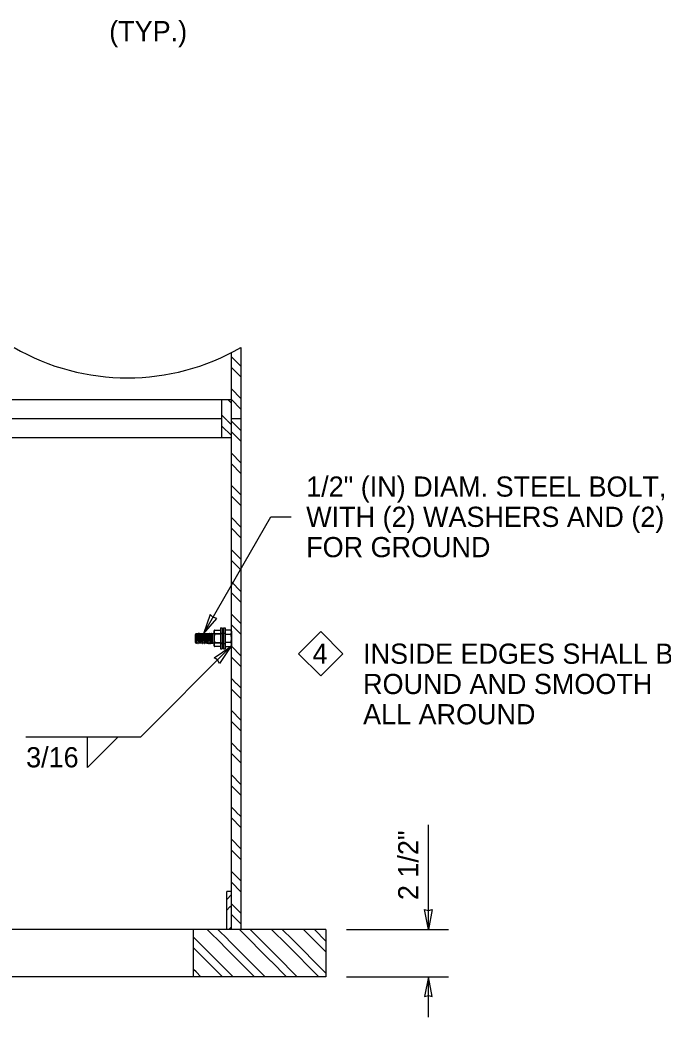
# Model space of a CAD drawing. Extents: x 99862 to 104211, y 98939 to 111076.
# Drawn here: x 101290 to 101800, y 109585 to 110375 of the extents above; entities that cross this region are included whole.
import ezdxf

# ---------------------------------------------------------------- set-up
doc = ezdxf.new("R2010")
doc.units = 0
for name, color, linetype in [('Level 10', 7, 'Continuous'), ('Level 11', 7, 'Continuous'), ('Level 15', 7, 'Continuous'), ('Level 2', 7, 'Continuous'), ('Level 20', 7, 'Continuous'), ('Level 3', 7, 'Continuous'), ('Level 5', 7, 'Continuous'), ('Level 62', 7, 'Continuous'), ('Level 9', 7, 'Continuous')]:
    doc.layers.add(name, color=color, linetype=linetype)

msp = doc.modelspace()

# ---------------------------------------------------------------- linework, layer by layer
at = {"layer": 'Level 11'}
for p, q in [((101457.91, 110108.52), (101461.88, 110104.55)), ((101461.9, 110104.53), (101465.41, 110101.02)), ((101457.91, 110100.03), (101465.41, 110092.53)), ((101457.91, 110083.02), (101465.41, 110075.52)), ((101457.91, 110074.53), (101465.41, 110067.03)), ((101457.91, 110057.52), (101461.86, 110053.57)), ((101457.91, 110049.03), (101465.41, 110041.53)), ((101461.88, 110053.55), (101465.41, 110050.02)), ((101457.91, 110032.02), (101465.41, 110024.52)), ((101457.91, 110023.53), (101465.41, 110016.03)), ((101457.91, 110006.52), (101461.83, 110002.59)), ((101461.86, 110002.57), (101465.41, 109999.02)), ((101457.91, 109998.03), (101465.41, 109990.53)), ((101457.91, 109981.02), (101465.41, 109973.52)), ((101457.91, 109972.53), (101465.41, 109965.03)), ((101457.91, 109955.52), (101461.81, 109951.61)), ((101457.91, 109947.03), (101465.41, 109939.53)), ((101461.83, 109951.59), (101465.41, 109948.02)), ((101457.91, 109930.02), (101465.41, 109922.52)), ((101457.91, 109921.53), (101465.41, 109914.03)), ((101457.91, 109904.52), (101461.79, 109900.64)), ((101461.81, 109900.61), (101465.41, 109897.02)), ((101457.91, 109896.03), (101465.41, 109888.53)), ((101457.91, 109879.02), (101465.41, 109871.52)), ((101457.91, 109870.53), (101465.41, 109863.03)), ((101457.91, 109853.52), (101461.77, 109849.66)), ((101457.91, 109845.03), (101465.41, 109837.53)), ((101461.79, 109849.64), (101465.41, 109846.02)), ((101457.91, 109828.02), (101465.41, 109820.52)), ((101457.91, 109819.53), (101465.41, 109812.03)), ((101457.91, 109802.52), (101461.74, 109798.68)), ((101461.77, 109798.66), (101465.41, 109795.02)), ((101457.91, 109794.03), (101465.41, 109786.53)), ((101457.91, 109777.02), (101465.41, 109769.52)), ((101457.91, 109768.53), (101465.41, 109761.03)), ((101457.91, 109751.52), (101461.72, 109747.7)), ((101457.91, 109743.03), (101465.41, 109735.53)), ((101461.74, 109747.68), (101465.41, 109744.02)), ((101457.91, 109726.02), (101465.41, 109718.52)), ((101457.91, 109717.53), (101465.41, 109710.03)), ((101457.91, 109700.52), (101461.7, 109696.72)), ((101461.72, 109696.7), (101465.41, 109693.02)), ((101457.91, 109692.03), (101465.41, 109684.53)), ((101454.16, 109678.43), (101457.91, 109682.18)), ((101454.16, 109669.95), (101456.61, 109672.4)), ((101456.64, 109672.43), (101457.91, 109673.7)), ((101457.91, 109675.02), (101465.41, 109667.52)), ((101457.91, 109666.53), (101465.41, 109659.03)), ((101427.91, 109654.65), (101142.91, 109654.65)), ((101451.06, 109642.27), (101438.68, 109654.65)), ((101455.3, 109646.51), (101447.17, 109654.65)), ((101455.87, 109654.65), (101457.91, 109656.68)), ((101489.28, 109629.54), (101464.18, 109654.65)), ((101493.53, 109633.79), (101472.67, 109654.65)), ((101502.03, 109642.29), (101489.68, 109654.65)), ((101506.28, 109646.54), (101498.17, 109654.65)), ((101532.91, 109636.92), (101515.18, 109654.65)), ((101532.91, 109645.41), (101523.67, 109654.65)), ((101442.55, 109633.76), (101427.91, 109648.41)), ((101480.78, 109621.04), (101455.32, 109646.49)), ((101531.75, 109621.06), (101506.3, 109646.51)), ((101438.31, 109629.52), (101427.91, 109639.92)), ((101476.18, 109617.15), (101451.08, 109642.25)), ((101527.18, 109617.15), (101502.06, 109642.27)), ((101459.17, 109617.15), (101442.57, 109633.74)), ((101510.17, 109617.15), (101493.55, 109633.76)), ((101429.8, 109621.01), (101427.91, 109622.9)), ((101450.68, 109617.15), (101438.33, 109629.5)), ((101501.68, 109617.15), (101489.31, 109629.52)), ((101427.91, 109617.15), (101142.91, 109617.15)), ((101433.67, 109617.15), (101429.82, 109620.99)), ((101484.67, 109617.15), (101480.8, 109621.01)), ((101532.91, 109619.91), (101531.78, 109621.04))]:
    msp.add_line(p, q, dxfattribs=at)
at = {"layer": 'Level 15'}
for p, q in [((101435.72, 109889.02), (101489.19, 109981.64)), ((101489.2, 109981.64), (101505.2, 109981.64)), ((101457.48, 109878.81), (101385.74, 109807.08)), ((101385.74, 109807.08), (101294.8, 109807.08)), ((101343.65, 109783.08), (101367.65, 109807.08)), ((101343.65, 109783.08), (101343.65, 109807.08)), ((101614.16, 109654.65), (101614.16, 109737.64)), ((101549.22, 109654.65), (101630.16, 109654.65)), ((101549.22, 109617.15), (101630.16, 109617.15)), ((101614.16, 109585.15), (101614.16, 109617.15))]:
    msp.add_line(p, q, dxfattribs=at)
for points in [[(101435.72, 109889.02), (101446.25, 109901.1), (101443.22, 109902.01), (101440.91, 109904.19)], [(101457.48, 109878.81), (101448.54, 109865.51), (101446.87, 109868.21), (101444.18, 109869.87)], [(101614.16, 109654.65), (101611.07, 109670.37), (101614.16, 109669.64), (101617.24, 109670.37)], [(101614.16, 109617.15), (101611.07, 109601.42), (101614.16, 109602.15), (101617.24, 109601.42)]]:
    msp.add_lwpolyline(points, close=True, dxfattribs=at)
at = {"layer": 'Level 2'}
for p, q in [((101427.91, 109617.15), (101427.91, 109654.65)), ((101532.91, 109654.65), (101427.91, 109654.65)), ((101532.91, 109654.65), (101532.91, 109617.15)), ((101532.91, 109617.15), (101427.91, 109617.15))]:
    msp.add_line(p, q, dxfattribs=at)
msp.add_lwpolyline([(101457.48, 109878.81), (101457.92, 109878.81), (101457.92, 109879.59)], close=True, dxfattribs=at)
at = {"layer": 'Level 20'}
msp.add_lwpolyline([(101528.78, 109890.72), (101546.34, 109873.17), (101528.78, 109855.62), (101511.23, 109873.17)], close=True, dxfattribs=at)
at = {"layer": 'Level 3'}
for p, q in [((101457.91, 109654.65), (101457.91, 110111.8)), ((101465.41, 110115.9), (101465.41, 109654.65)), ((101112.91, 110074.65), (101457.91, 110074.65)), ((101450.41, 110044.65), (101450.41, 110074.65)), ((101457.91, 110071.68), (101454.94, 110074.65)), ((101120.41, 110059.65), (101450.41, 110059.65)), ((101454.36, 110058.16), (101450.41, 110062.12)), ((101457.91, 110054.62), (101454.41, 110058.12)), ((101457.91, 110059.65), (101465.41, 110059.65)), ((101457.91, 110046.13), (101450.41, 110053.63)), ((101112.91, 110044.65), (101457.91, 110044.65)), ((101454.16, 109654.65), (101454.16, 109684.65)), ((101457.91, 109684.65), (101454.16, 109684.65)), ((101465.41, 109654.65), (101457.91, 109654.65))]:
    msp.add_line(p, q, dxfattribs=at)
msp.add_arc((101375.41, 110271.78), 180, 240, 300, dxfattribs=at)
at = {"layer": 'Level 5'}
for p, q in [((101429.77, 109889.02), (101429.77, 109881.52)), ((101451.6, 109889.02), (101429.77, 109889.02)), ((101449.1, 109889.05), (101449.1, 109881.55)), ((101451.6, 109889.02), (101451.6, 109881.52)), ((101452.91, 109889.05), (101452.91, 109881.55)), ((101451.6, 109881.52), (101429.77, 109881.52))]:
    msp.add_line(p, q, dxfattribs=at)
at = {"layer": 'Level 62'}
for points, degree in [([(101429.77, 109885.18), (101429.87, 109883.56), (101429.95, 109882.35), (101430.01, 109881.81), (101430.14, 109880.61), (101430.28, 109882.61), (101430.43, 109885.81), (101430.5, 109887.51), (101430.59, 109888.84), (101430.7, 109889.02)], 4), ([(101429.77, 109885.22), (101429.77, 109885.21), (101429.77, 109885.2), (101429.77, 109885.18)], 3), ([(101430.7, 109889.02), (101430.75, 109889.12), (101430.8, 109888.82), (101430.84, 109888.26), (101430.97, 109886.29), (101431.12, 109883.09), (101431.25, 109881.83), (101431.39, 109880.58), (101431.53, 109882.53), (101431.67, 109885.73), (101431.81, 109888.95), (101431.94, 109890.23), (101432.08, 109888.31), (101432.22, 109886.39), (101432.37, 109883.18), (101432.5, 109881.86), (101432.64, 109880.55), (101432.77, 109882.44), (101432.92, 109885.67)], 4), ([(101432.92, 109885.67), (101432.99, 109887.43), (101433.08, 109888.84), (101433.2, 109889.02)], 3), ([(101433.2, 109889.02), (101433.25, 109889.11), (101433.3, 109888.85), (101433.34, 109888.35), (101433.47, 109886.48), (101433.61, 109883.26), (101433.74, 109881.9), (101433.88, 109880.52), (101434.02, 109882.38), (101434.16, 109885.59), (101434.3, 109888.82), (101434.44, 109890.21), (101434.58, 109888.38), (101434.72, 109886.57), (101434.86, 109883.35), (101434.99, 109881.93), (101435.13, 109880.5), (101435.27, 109882.29), (101435.41, 109885.52), (101435.49, 109887.36), (101435.58, 109888.83), (101435.7, 109889.02)], 4), ([(101435.7, 109889.02), (101435.75, 109889.11), (101435.79, 109888.88), (101435.83, 109888.43), (101435.96, 109886.66), (101436.1, 109883.43), (101436.24, 109881.96), (101436.38, 109880.48), (101436.52, 109882.22), (101436.66, 109885.44), (101436.73, 109887.31), (101436.83, 109888.83), (101436.95, 109889.02)], 4), ([(101436.95, 109889.02), (101437, 109889.11), (101437.04, 109888.89), (101437.07, 109888.47), (101437.21, 109886.75), (101437.35, 109883.52), (101437.48, 109881.99), (101437.63, 109880.46), (101437.76, 109882.15), (101437.9, 109885.38), (101437.98, 109887.29), (101438.08, 109888.84), (101438.2, 109889.02)], 4), ([(101438.2, 109889.02), (101438.25, 109889.1), (101438.28, 109888.9), (101438.32, 109888.5), (101438.46, 109886.85), (101438.59, 109883.61), (101438.73, 109882.02), (101438.87, 109880.43), (101439.01, 109882.08), (101439.15, 109885.31), (101439.23, 109887.24), (101439.33, 109888.83), (101439.45, 109889.02)], 4), ([(101439.45, 109889.02), (101439.49, 109889.1), (101439.53, 109888.92), (101439.56, 109888.54), (101439.7, 109886.94), (101439.84, 109883.7), (101439.97, 109882.06), (101440.12, 109880.42), (101440.26, 109882), (101440.39, 109885.23), (101440.53, 109888.47), (101440.67, 109890.13), (101440.81, 109888.57), (101440.94, 109887.03), (101441.08, 109883.79), (101441.23, 109882.1), (101441.37, 109880.4), (101441.5, 109881.93), (101441.64, 109885.17), (101441.77, 109888.39), (101441.92, 109890.12), (101442.06, 109888.61), (101442.19, 109887.11), (101442.33, 109883.88), (101442.47, 109882.14), (101442.61, 109880.39), (101442.74, 109881.87), (101442.88, 109885.1), (101442.97, 109887.13), (101443.08, 109888.83), (101443.2, 109889.02)], 4)]:
    msp.add_open_spline(points, degree=degree, dxfattribs=at)
at = {"layer": 'Level 9'}
for p, q in [((101444.1, 109890.93), (101444.61, 109891.8)), ((101444.1, 109890.93), (101444.1, 109890.25)), ((101444.1, 109890.93), (101444.1, 109890.24)), ((101444.1, 109890.93), (101444.1, 109890.24)), ((101444.61, 109891.8), (101449.1, 109891.8)), ((101449.1, 109891.8), (101449.1, 109888.55)), ((101449.21, 109893.64), (101449.21, 109876.97)), ((101449.21, 109893.64), (101450.46, 109893.64)), ((101450.46, 109893.64), (101450.46, 109876.97)), ((101451.66, 109893.64), (101451.66, 109876.97)), ((101451.66, 109893.64), (101452.91, 109893.64)), ((101452.91, 109893.64), (101452.91, 109876.97)), ((101457.41, 109891.8), (101452.91, 109891.8)), ((101452.91, 109891.8), (101452.91, 109888.55)), ((101457.91, 109890.93), (101457.41, 109891.8)), ((101457.91, 109890.93), (101457.91, 109890.25)), ((101457.91, 109890.93), (101457.91, 109890.24)), ((101457.91, 109890.93), (101457.91, 109890.24)), ((101429.77, 109889.03), (101429.25, 109888.12)), ((101429.25, 109888.12), (101429.25, 109882.42)), ((101444.1, 109890.24), (101444.1, 109890.25)), ((101444.1, 109890.24), (101444.1, 109890.12)), ((101444.1, 109890.1), (101444.1, 109890.12)), ((101444.1, 109890.12), (101444.1, 109885.31)), ((101444.1, 109890.12), (101444.1, 109885.31)), ((101444.1, 109890.1), (101444.1, 109885.45)), ((101444.1, 109885.31), (101444.1, 109885.45)), ((101444.1, 109885.31), (101444.1, 109879.68)), ((101444.1, 109885.17), (101444.1, 109885.31)), ((101444.1, 109879.68), (101444.1, 109885.31)), ((101444.1, 109885.31), (101444.1, 109885.31)), ((101444.1, 109885.17), (101444.1, 109880.47)), ((101449.1, 109888.55), (101444.61, 109888.55)), ((101449.21, 109889.48), (101450.46, 109889.48)), ((101451.66, 109889.48), (101452.91, 109889.48)), ((101452.91, 109888.55), (101457.41, 109888.55)), ((101452.91, 109888.55), (101452.91, 109882.06)), ((101457.91, 109890.24), (101457.91, 109890.25)), ((101457.91, 109890.24), (101457.91, 109890.12)), ((101457.91, 109890.1), (101457.91, 109890.12)), ((101457.91, 109890.12), (101457.91, 109885.31)), ((101457.91, 109890.12), (101457.91, 109885.31)), ((101457.91, 109890.1), (101457.91, 109885.45)), ((101457.91, 109885.31), (101457.91, 109885.45)), ((101457.91, 109885.31), (101457.91, 109879.68)), ((101457.91, 109885.17), (101457.91, 109885.31)), ((101457.91, 109879.68), (101457.91, 109885.31)), ((101457.91, 109885.31), (101457.91, 109885.31)), ((101457.91, 109885.17), (101457.91, 109880.47)), ((101429.25, 109882.42), (101429.76, 109881.53)), ((101444.1, 109880.4), (101444.1, 109880.47)), ((101444.1, 109880.4), (101444.1, 109879.68)), ((101444.1, 109879.68), (101444.1, 109879.68)), ((101444.61, 109878.81), (101444.1, 109879.68)), ((101444.61, 109882.06), (101449.1, 109882.06)), ((101449.1, 109878.81), (101444.61, 109878.81)), ((101449.1, 109882.06), (101449.1, 109882.06)), ((101449.1, 109882.06), (101449.1, 109878.81)), ((101449.21, 109881.13), (101450.46, 109881.13)), ((101449.21, 109876.97), (101450.46, 109876.97)), ((101451.66, 109881.13), (101452.91, 109881.13)), ((101451.66, 109876.97), (101452.91, 109876.97)), ((101452.91, 109882.06), (101452.91, 109882.06)), ((101452.91, 109882.06), (101452.91, 109878.81)), ((101457.41, 109882.06), (101452.91, 109882.06)), ((101452.91, 109878.81), (101457.41, 109878.81)), ((101457.4, 109878.81), (101457.91, 109879.68)), ((101457.91, 109880.4), (101457.91, 109880.47)), ((101457.91, 109880.4), (101457.91, 109879.68)), ((101457.91, 109879.68), (101457.91, 109879.68))]:
    msp.add_line(p, q, dxfattribs=at)
for points, degree in [([(101444.1, 109890.24), (101444.1, 109890.25), (101444.11, 109890.27), (101444.11, 109890.29), (101444.13, 109890.8), (101444.32, 109891.31), (101444.61, 109891.8)], 3), ([(101444.61, 109891.8), (101444.31, 109891.29), (101444.12, 109890.78), (101444.1, 109890.25)], 2), ([(101444.1, 109890.24), (101444.12, 109890.77), (101444.31, 109891.29), (101444.61, 109891.8)], 2), ([(101444.61, 109891.8), (101444.61, 109891.8), (101444.61, 109891.8), (101444.61, 109891.8)], 2), ([(101457.91, 109890.24), (101457.91, 109890.25), (101457.91, 109890.27), (101457.91, 109890.29), (101457.88, 109890.8), (101457.69, 109891.31), (101457.41, 109891.8)], 3), ([(101457.41, 109891.8), (101457.41, 109891.8), (101457.41, 109891.8), (101457.41, 109891.8)], 2), ([(101457.41, 109891.8), (101457.7, 109891.29), (101457.89, 109890.78), (101457.91, 109890.25)], 2), ([(101457.91, 109890.24), (101457.89, 109890.77), (101457.7, 109891.29), (101457.41, 109891.8)], 2), ([(101429.76, 109881.53), (101429.76, 109881.53), (101429.76, 109881.85), (101429.77, 109883.07), (101429.77, 109884.01), (101429.77, 109885.96), (101429.77, 109886.96), (101429.77, 109888.47), (101429.77, 109888.94), (101429.77, 109889.03), (101429.77, 109889.03), (101429.77, 109889.02)], 3), ([(101429.77, 109888.13), (101429.77, 109887.48), (101429.77, 109886.54), (101429.77, 109884.59), (101429.77, 109883.58), (101429.77, 109882.1), (101429.76, 109881.62), (101429.76, 109881.53), (101429.76, 109881.53), (101429.76, 109881.53)], 3), ([(101429.77, 109889.02), (101429.77, 109888.98), (101429.77, 109888.67), (101429.77, 109888.13)], 2), ([(101429.77, 109889.02), (101429.77, 109889.02), (101429.77, 109889.02), (101429.77, 109889.02)], 2), ([(101444.61, 109888.55), (101444.31, 109889.06), (101444.12, 109889.59), (101444.1, 109890.12)], 2), ([(101444.61, 109888.55), (101444.31, 109889.07), (101444.12, 109889.59), (101444.1, 109890.12)], 2), ([(101444.1, 109885.31), (101444.1, 109886.14), (101444.22, 109886.98), (101444.41, 109887.8), (101444.47, 109888.05), (101444.53, 109888.3), (101444.61, 109888.55)], 3), ([(101444.61, 109888.55), (101444.3, 109887.5), (101444.1, 109886.4), (101444.1, 109885.31)], 2), ([(101444.61, 109882.06), (101444.38, 109882.85), (101444.21, 109883.66), (101444.14, 109884.47), (101444.12, 109884.75), (101444.1, 109885.03), (101444.1, 109885.31)], 3), ([(101444.1, 109885.31), (101444.1, 109884.21), (101444.3, 109883.11), (101444.61, 109882.06)], 2), ([(101444.61, 109882.06), (101444.57, 109882.2), (101444.53, 109882.34), (101444.49, 109882.48), (101444.25, 109883.4), (101444.1, 109884.35), (101444.1, 109885.31)], 3), ([(101457.41, 109888.55), (101457.7, 109889.06), (101457.89, 109889.59), (101457.91, 109890.12)], 2), ([(101457.41, 109888.55), (101457.7, 109889.07), (101457.89, 109889.59), (101457.91, 109890.12)], 2), ([(101457.91, 109885.31), (101457.91, 109886.14), (101457.79, 109886.98), (101457.6, 109887.8), (101457.54, 109888.05), (101457.48, 109888.3), (101457.41, 109888.55)], 3), ([(101457.41, 109888.55), (101457.71, 109887.5), (101457.91, 109886.4), (101457.91, 109885.31)], 2), ([(101457.41, 109882.06), (101457.63, 109882.85), (101457.8, 109883.66), (101457.87, 109884.47), (101457.9, 109884.75), (101457.91, 109885.03), (101457.91, 109885.31)], 3), ([(101457.91, 109885.31), (101457.91, 109884.21), (101457.71, 109883.11), (101457.41, 109882.06)], 2), ([(101457.41, 109882.06), (101457.45, 109882.2), (101457.48, 109882.34), (101457.52, 109882.48), (101457.76, 109883.4), (101457.91, 109884.35), (101457.91, 109885.31)], 3), ([(101444.61, 109878.81), (101444.28, 109879.37), (101444.08, 109879.96), (101444.11, 109880.55), (101444.13, 109881.06), (101444.32, 109881.57), (101444.61, 109882.06)], 3), ([(101444.61, 109878.81), (101444.3, 109879.34), (101444.1, 109879.88), (101444.1, 109880.98), (101444.3, 109881.53), (101444.61, 109882.06)], 3), ([(101444.1, 109880.4), (101444.1, 109880.4), (101444.1, 109880.4), (101444.1, 109880.4)], 2), ([(101444.1, 109880.4), (101444.11, 109879.86), (101444.31, 109879.33), (101444.61, 109878.81)], 2), ([(101444.61, 109878.81), (101444.61, 109878.81), (101444.61, 109878.81), (101444.61, 109878.81)], 2), ([(101457.41, 109878.81), (101457.73, 109879.37), (101457.93, 109879.96), (101457.9, 109880.55), (101457.88, 109881.06), (101457.69, 109881.57), (101457.41, 109882.06)], 3), ([(101457.41, 109878.81), (101457.71, 109879.34), (101457.91, 109879.88), (101457.91, 109880.98), (101457.71, 109881.53), (101457.41, 109882.06)], 3), ([(101457.91, 109880.4), (101457.9, 109879.86), (101457.7, 109879.33), (101457.41, 109878.81)], 2), ([(101457.41, 109878.81), (101457.41, 109878.81), (101457.41, 109878.81), (101457.41, 109878.81)], 2), ([(101457.91, 109880.4), (101457.91, 109880.4), (101457.91, 109880.4), (101457.91, 109880.4)], 2)]:
    msp.add_open_spline(points, degree=degree, dxfattribs=at)

# ---------------------------------------------------------------- texts
at = {"layer": 'Level 10'}
msp.add_text('3/16', height=16, rotation=360, dxfattribs=at).set_placement((101295.02, 109783.08))
at = {"layer": 'Level 20'}
for s, p in [('(TYP.)', (101360.94, 110358.65)), ('1/2" (IN) DIAM. STEEL BOLT, 1 1/2" (IN) LONG,', (101517.2, 109997.65)), ('WITH (2) WASHERS AND (2) NUTS ', (101517.2, 109973.65)), ('FOR GROUND', (101517.2, 109949.65)), ('4', (101522.28, 109865.17)), ('INSIDE EDGES SHALL BE', (101562.34, 109865.17)), ('ROUND AND SMOOTH ', (101562.34, 109841.17)), ('ALL AROUND', (101562.34, 109817.17))]:
    msp.add_text(s, height=16, dxfattribs=at).set_placement(p)
msp.add_text('2 1/2"', height=16, rotation=90, dxfattribs=at).set_placement((101606.16, 109677.86))

doc.saveas('drawing.dxf')
